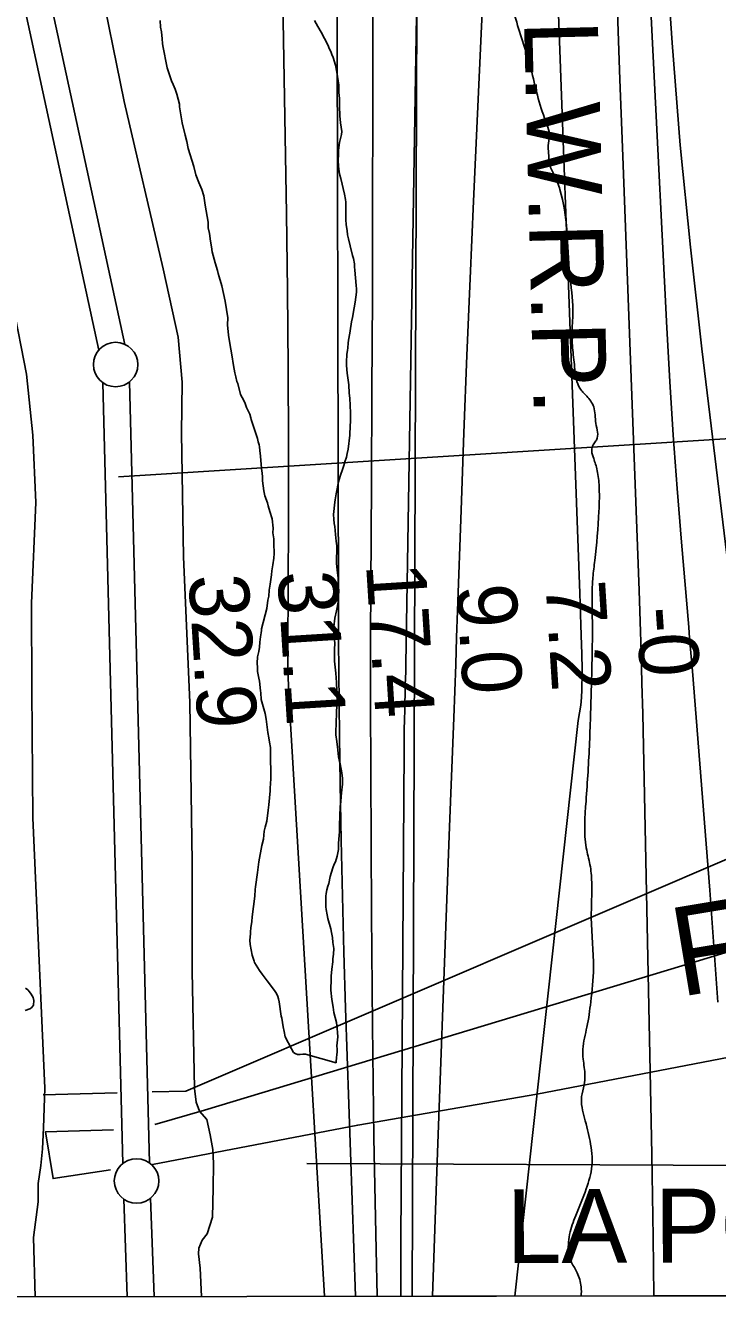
# Model space of a CAD drawing. Extents: x 3313442 to 3351311, y 721974 to 747360.
# Drawn here: x 3321997 to 3322775, y 727351 to 728787 of the extents above; entities that cross this region are included whole.
import ezdxf

# ---------------------------------------------------------------- set-up
doc = ezdxf.new("R2010")
doc.units = 0
for name, color, linetype in [('V-CHAN-NAID', 7, 'Continuous'), ('V-GRID-FRAM', 7, 'Continuous'), ('V-LEVE-TOET', 7, 'Continuous'), ('V-RIVR-EDGE', 7, 'Continuous'), ('V-RIVR-RANG', 7, 'Continuous'), ('V-RRAP-FSHR', 7, 'Continuous'), ('V-SITE-VEGE', 7, 'Continuous'), ('V-SURV-LINE', 7, 'Continuous'), ('V-TOPO-DPTH', 7, 'Continuous'), ('V-TOPO-MAJR', 7, 'Continuous'), ('V-TOPO-MINR', 7, 'Continuous'), ('V-TOPO-WATR', 7, 'Continuous'), ('V-TOPO-WATR-IDEN', 7, 'Continuous'), ('V-UTIL-IDEN', 7, 'Continuous'), ('V-UTIL-LINE', 7, 'Continuous')]:
    doc.layers.add(name, color=color, linetype=linetype)

msp = doc.modelspace()

# ---------------------------------------------------------------- linework, layer by layer
at = {"layer": 'V-GRID-FRAM'}
msp.add_lwpolyline([(3317558.4, 745536.3), (3349037, 745582.1), (3349071.4, 727396.8), (3317576.9, 727351), (3317558.4, 745536.3)], dxfattribs=at)
at = {"layer": 'V-LEVE-TOET'}
for points in [[(3322194.5, 727357.7), (3322192.8, 727389.4), (3322191.2, 727405.8), (3322191.6, 727411.9), (3322195, 727421.1), (3322200.8, 727428.3), (3322206.6, 727446.9), (3322207.4, 727479.7), (3322208, 727507.4), (3322207.1, 727523.1), (3322204.3, 727539.4), (3322200.4, 727556.6), (3322192.3, 727566.3), (3322188.6, 727576.1), (3322186.6, 727591.5), (3322184.1, 727723.8), (3322183.8, 727846.4), (3322181.2, 728025.8), (3322174, 728189.6), (3322172, 728328.7), (3322172.5, 728385.9), (3322168.1, 728436.7), (3322151.4, 728513.4), (3322107.3, 728701.9), (3322077.7, 728847.6)], [(3321914.5, 728813), (3321936.1, 728698.3), (3321966.6, 728552.6), (3321997.7, 728394.9), (3322004.8, 728326.6), (3322008.2, 728250.6), (3322003.2, 728137.7), (3322003.5, 728039.9), (3322004.9, 727896), (3322013.6, 727693.4), (3322018.2, 727592), (3322016.8, 727547.4), (3322015.7, 727523.9), (3322013.9, 727505.1), (3322010.8, 727484.9), (3322010.6, 727464.3), (3322005.5, 727424.2), (3322007.5, 727357.5)]]:
    msp.add_lwpolyline(points, dxfattribs=at)
at = {"layer": 'V-RIVR-EDGE'}
msp.add_spline([(3322512.8, 729081.8), (3322515.6, 729043.4), (3322518.8, 728981.6), (3322524.4, 728921.9), (3322530.2, 728886.2), (3322534.6, 728860.1), (3322542, 728820.3), (3322546.9, 728797.9), (3322563.8, 728741.9), (3322580.2, 728683), (3322585.6, 728662.7), (3322584.3, 728652.3), (3322584.7, 728644), (3322585.9, 728630.8), (3322591.3, 728618.7), (3322597.4, 728602.6), (3322605.2, 728557), (3322608.4, 728506.8), (3322612, 728467.4), (3322611.1, 728443.4), (3322611.9, 728422.2), (3322614.3, 728400.3), (3322619.7, 728379.5), (3322627.5, 728370.4), (3322635.4, 728358.3), (3322637.8, 728339.7), (3322638.6, 728321), (3322635.7, 728316.9), (3322633.2, 728311.1), (3322634.8, 728302), (3322638.9, 728288.7), (3322641.4, 728270.9), (3322641.3, 728240.6), (3322636.6, 728185.5), (3322634.5, 728166.4), (3322633.9, 728116.3), (3322632.9, 728048.3), (3322630.7, 727980.8), (3322629, 727948), (3322626.8, 727914.9), (3322627.1, 727862.2), (3322631.2, 727843.6), (3322633.2, 727823.7), (3322632.7, 727783.5), (3322635.1, 727727.1), (3322632.1, 727689), (3322627.8, 727660.8), (3322623.2, 727635.9), (3322623.6, 727624.7), (3322625.6, 727606.1), (3322624.8, 727595.7), (3322621.8, 727582.5), (3322625.1, 727558.4), (3322631.3, 727532.3), (3322633.3, 727504.5), (3322627, 727478.8), (3322615.3, 727449), (3322608.2, 727427.5), (3322606.9, 727415.9), (3322606.9, 727408.4), (3322610.6, 727396), (3322616.8, 727384.4), (3322621.3, 727368.6), (3322621.4, 727358.3)], degree=3, dxfattribs=at)
at = {"layer": 'V-RIVR-RANG'}
msp.add_line((3322101.2, 728279.7), (3322899.6, 728329.5), dxfattribs=at)
at = {"layer": 'V-RRAP-FSHR'}
msp.add_lwpolyline([(3322437.9, 729220.8), (3322431.3, 727358.1)], dxfattribs=at)
at = {"layer": 'V-SITE-VEGE'}
for points in [[(3322228.4, 728416.9), (3322226.1, 728429.7), (3322224.9, 728438.8), (3322223.8, 728450.4), (3322223.9, 728458.6), (3322221.1, 728477.2), (3322217.2, 728494.6), (3322214.4, 728504.5), (3322213.2, 728508.2), (3322212.4, 728511.6), (3322209.6, 728520.2), (3322206.4, 728532.7), (3322205.6, 728538.4), (3322204.5, 728544.6), (3322203.3, 728553.3), (3322202.1, 728559.5), (3322201.8, 728566.1), (3322198.6, 728585.1), (3322197.1, 728595.5), (3322194.7, 728602.9), (3322191.5, 728610.8), (3322188.2, 728619.1), (3322185.8, 728628.6), (3322179.4, 728648.9), (3322177.9, 728656.7), (3322175.9, 728663.8), (3322172.7, 728677.8), (3322169.6, 728695.6), (3322169.6, 728698.9), (3322166.8, 728710.1), (3322164.8, 728715.5), (3322162.4, 728720.8), (3322160.8, 728725), (3322157.9, 728732.9), (3322155.9, 728739.5), (3322150.8, 728764.3), (3322150.4, 728766.8), (3322150.1, 728772.1), (3322149.3, 728780), (3322148.5, 728785.3), (3322147.8, 728792.8)], [(3322321.5, 728792.8), (3322325.1, 728786.1), (3322329.1, 728779.6), (3322336.5, 728765.5), (3322338.3, 728760.6), (3322339.7, 728757.8), (3322341.1, 728754.5), (3322342.3, 728751.3), (3322344.9, 728742.6), (3322346.7, 728734.7), (3322348.7, 728720.3), (3322349, 728711.9), (3322349.4, 728705.2), (3322349.4, 728696.4), (3322350, 728685.5), (3322350.8, 728677.7), (3322352.3, 728668), (3322351.8, 728664.8), (3322350.6, 728660.3), (3322349.7, 728655.7), (3322348.9, 728649.9), (3322348.3, 728646.5), (3322348.3, 728642.6), (3322348.1, 728635.4), (3322348.4, 728629.1), (3322349.2, 728622.6), (3322349.9, 728618.8), (3322350.9, 728615.1), (3322355.2, 728597.6), (3322356.3, 728591.7), (3322356.6, 728588.4), (3322356.7, 728583), (3322356.6, 728568.9), (3322356.9, 728563.1), (3322358.1, 728556.6), (3322358.6, 728551.8), (3322359.6, 728547.1), (3322361.7, 728539.5), (3322364.3, 728528.6), (3322365.3, 728525.1), (3322366.4, 728519.2), (3322366.3, 728515.8), (3322367, 728512), (3322368.5, 728494.8), (3322368.6, 728491), (3322368.6, 728487.4), (3322367.2, 728476.1), (3322365.9, 728469.6), (3322364.2, 728458.7), (3322363.2, 728454), (3322361.5, 728443.8), (3322361.3, 728441.3), (3322359.6, 728433.2), (3322359.4, 728429.8), (3322358.8, 728424.8), (3322358.6, 728421.6), (3322357.9, 728417.5), (3322357.4, 728408.7), (3322357.6, 728404.7), (3322358.2, 728396.1), (3322360, 728383), (3322360.5, 728373.6), (3322361.2, 728368.2), (3322361.9, 728351.5), (3322361.8, 728341.5), (3322361.4, 728337.3), (3322361.1, 728326.4), (3322359.5, 728310.8), (3322358.2, 728305.9), (3322357.3, 728301.8), (3322355.6, 728296.3), (3322354.3, 728292.5), (3322353.4, 728288.9), (3322350.5, 728280.3), (3322348.6, 728274.1), (3322345.8, 728260.6), (3322344.8, 728253.6), (3322343.9, 728248.1), (3322343.5, 728244.1), (3322343, 728237.1), (3322343.2, 728232.1), (3322343.7, 728227.2), (3322344.2, 728223.8), (3322345.2, 728214.8), (3322345.8, 728207.3)], [(3322281, 727692.6), (3322280.2, 727695), (3322278.6, 727698.4), (3322276.5, 727701.7), (3322268.4, 727712.9), (3322262.7, 727720.4), (3322259.8, 727724.5), (3322254.1, 727733.3), (3322253.8, 727734.9), (3322251.3, 727741.5), (3322249, 727753.5), (3322248.6, 727758.5), (3322249.5, 727765.5), (3322249.5, 727768), (3322250, 727772.5), (3322250.9, 727779.5), (3322251.3, 727784.9), (3322252.7, 727796.4), (3322254.4, 727808), (3322254.9, 727815.4), (3322255, 727818.3), (3322257.2, 727834.7), (3322258.9, 727846.7), (3322262.4, 727864.8), (3322264.1, 727872.2), (3322265, 727880.9), (3322265.9, 727885.4), (3322268, 727892.4), (3322269.4, 727904.8), (3322270.3, 727910.6), (3322271.7, 727926.6), (3322271.7, 727929.5), (3322272.2, 727939.8), (3322272.3, 727946), (3322272, 727964.2), (3322272.1, 727975.3), (3322270.9, 727981.1), (3322270.2, 727986.1), (3322269, 727991.9), (3322267, 728007.2), (3322265.9, 728013.4), (3322261.5, 728029.1), (3322261.1, 728036.5), (3322260.7, 728039), (3322259.6, 728049.7), (3322258.8, 728053), (3322257.2, 728060.5), (3322257.3, 728065), (3322256.9, 728070), (3322257.4, 728077), (3322258.7, 728083.2), (3322259.6, 728088.1), (3322260, 728093.5), (3322260.9, 728099.7), (3322261.4, 728104.2), (3322261.8, 728106.7), (3322261.8, 728108.7), (3322267.8, 728131.4), (3322269.1, 728140.8), (3322270, 728145.4), (3322270.5, 728152), (3322271.8, 728159), (3322273.1, 728169.3), (3322273.6, 728173.8), (3322274.5, 728180.8), (3322275.8, 728188.2), (3322276.2, 728193.2), (3322275.9, 728204.7), (3322275.6, 728209.7), (3322274.8, 728216.7), (3322274.9, 728221.7), (3322273.7, 728232.4), (3322271.3, 728240.7), (3322269.3, 728246.9), (3322268.5, 728250.2), (3322265.7, 728258.1), (3322264.5, 728263.9), (3322263, 728275), (3322263, 728279.6), (3322262.6, 728283.7), (3322261.9, 728289.1), (3322260.8, 728302.7), (3322260, 728309.3), (3322259.6, 728313.4), (3322259.2, 728315.5), (3322258, 728318.8), (3322257.2, 728322.9), (3322256, 728327.1), (3322250.4, 728344.1), (3322250, 728346.1), (3322248.8, 728349.9), (3322245.2, 728357.7), (3322243.2, 728363.1), (3322240.3, 728368.9), (3322238.3, 728372.2), (3322235.1, 728384.6), (3322234.3, 728386.7), (3322233.1, 728392.1), (3322231.9, 728396.6), (3322230.4, 728404.9), (3322228.4, 728416.9)], [(3322345.8, 728207.3), (3322346.5, 728202.1), (3322346.3, 728182.1), (3322347.1, 728174.9), (3322347.9, 728165.8), (3322348.1, 728160.4), (3322348.7, 728151), (3322348.5, 728145.7), (3322347.9, 728138.5), (3322346.3, 728128.8), (3322344.5, 728120.7), (3322343.1, 728111), (3322343.1, 728105.3), (3322343.4, 728099.2), (3322344.2, 728092.7), (3322343.8, 728085.5), (3322343.9, 728080.3), (3322343.8, 728072.2), (3322345.5, 728058.8), (3322346.1, 728048.3), (3322346.4, 728039), (3322346.9, 728035.8), (3322346.8, 728025), (3322346.2, 728016.4), (3322346.1, 728011.2), (3322345.7, 728006), (3322345.6, 727989.4), (3322346.6, 727982.1), (3322347.6, 727972.4), (3322348.6, 727964.8), (3322349.6, 727959.6), (3322350.5, 727956.7), (3322352.2, 727946.6), (3322352.8, 727940.2), (3322352.9, 727934.1), (3322352.7, 727930.5), (3322352.2, 727927.4), (3322351.4, 727920.1), (3322351.1, 727914), (3322350.5, 727908.8), (3322349.6, 727887.8), (3322349.7, 727880.8), (3322349.2, 727876.1), (3322348.4, 727867.5), (3322348.3, 727860.3), (3322346.8, 727852.9), (3322344.9, 727846.7), (3322343.6, 727844), (3322342.2, 727839.9), (3322339.2, 727830.2), (3322337.5, 727822.3), (3322336.4, 727819.1), (3322335.5, 727815), (3322334.7, 727811), (3322334.3, 727807.8), (3322334.3, 727801.3), (3322334.4, 727796.1), (3322334.7, 727793.1), (3322335.6, 727787.1), (3322336.6, 727782.8), (3322339.7, 727771.3), (3322340.6, 727767.2), (3322341.6, 727761.6), (3322342.1, 727755.7), (3322343.1, 727749), (3322343, 727742.7), (3322342.1, 727737.5), (3322341.9, 727734.1), (3322340.9, 727726), (3322340.7, 727721.9), (3322340.3, 727718.5), (3322340.1, 727715.4), (3322340, 727702.3), (3322340.8, 727691.9), (3322342.3, 727683.1), (3322343.1, 727677.2), (3322346.3, 727665.8), (3322347.1, 727659), (3322347.4, 727654.5), (3322347.6, 727649.8), (3322346.7, 727639.6), (3322346.9, 727635.8), (3322346.9, 727632.8), (3322346.6, 727629.7), (3322346.1, 727626.7), (3322345.9, 727621.8), (3322345.7, 727620.7), (3322311.4, 727630.4), (3322308.5, 727630.4), (3322305.2, 727630), (3322302.3, 727630), (3322299.8, 727630.9), (3322297.8, 727632.2), (3322295.7, 727636.3), (3322288.4, 727649.6), (3322287.3, 727655.8), (3322286.1, 727661.1), (3322284.9, 727670.7), (3322284.1, 727673.1), (3322281.8, 727689.3), (3322281, 727692.6)], [(3321996.5, 727704.5), (3321999, 727702.7), (3322001.2, 727700.2), (3322003, 727697.6), (3322005, 727694.1), (3322006, 727690.8), (3322005.7, 727685.5), (3322003.1, 727682.4), (3322001.3, 727681.2), (3321996.2, 727679.5)]]:
    msp.add_lwpolyline(points, dxfattribs=at)
at = {"layer": 'V-SURV-LINE'}
for points in [[(3322079, 728422.2), (3321968.5, 728932.8)], [(3321997.8, 728939.2), (3322108.3, 728428.6)], [(3322113.3, 728386.3), (3322135.8, 727508.1)], [(3322105.8, 727507.3), (3322083.4, 728385.5)], [(3322111, 727357.6), (3322107.1, 727467.2)], [(3322137.1, 727468.3), (3322141.1, 727357.6)]]:
    msp.add_lwpolyline(points, dxfattribs=at)
for centre in [(3322097.8, 728405.9), (3322121.4, 727487.7)]:
    msp.add_circle(centre, 25, dxfattribs=at)
at = {"layer": 'V-TOPO-DPTH'}
for points in [[(3322521, 729040.3), (3322500.3, 728589.5), (3322496.5, 728502.7), (3322492.9, 728415.9), (3322489.5, 728329.1), (3322486.3, 728242.3), (3322482.4, 728128.8), (3322481.3, 728098.8), (3322480.2, 728068.7), (3322479.1, 728038.7), (3322478, 728008.7), (3322473.2, 727885.8), (3322469.8, 727794.3), (3322466.4, 727702.8), (3322463.1, 727611.3), (3322459.8, 727519.8), (3322454.2, 727358.1), (3322702.9, 727358.5)], [(3322715.8, 728882.5), (3322723.6, 728767.6), (3322732.8, 728652.7), (3322744.2, 728538.1), (3322756.9, 728423.5), (3322788, 728166.6)], [(3322715.8, 728882.5), (3322723.6, 728767.6), (3322732.8, 728652.7), (3322744.2, 728538.1), (3322756.9, 728423.5), (3322788, 728166.6)], [(3322702.9, 727358.5), (3322702.1, 727424.3), (3322700.6, 727517.6), (3322698.8, 727610.9), (3322690.5, 728013), (3322689.7, 728047.6), (3322688.7, 728082.3), (3322687.6, 728116.9), (3322686.4, 728151.6), (3322667.7, 728650.1), (3322664.9, 728726.4), (3322662.1, 728802.7)], [(3322702.9, 727358.5), (3322702.1, 727424.3), (3322700.6, 727517.6), (3322698.8, 727610.9), (3322690.5, 728013), (3322689.7, 728047.6), (3322688.7, 728082.3), (3322687.6, 728116.9), (3322686.4, 728151.6), (3322667.7, 728650.1), (3322664.9, 728726.4), (3322662.1, 728802.7)], [(3322861.6, 727358.7), (3322702.9, 727358.5)]]:
    msp.add_lwpolyline(points, dxfattribs=at)
at = {"layer": 'V-TOPO-MAJR'}
msp.add_lwpolyline([(3322346.5, 728937), (3322348.4, 728132), (3322348.6, 728096.1), (3322348.8, 728060.2), (3322349.2, 728024.3), (3322349.6, 727988.3), (3322350.4, 727934.1), (3322351.5, 727871.1), (3322352.8, 727808.1), (3322354.5, 727745.1), (3322356.5, 727682.1), (3322367.4, 727358)], dxfattribs=at)
at = {"layer": 'V-TOPO-MINR'}
for points in [[(3322440.2, 729049.6), (3322424.2, 728069), (3322424.2, 728065.1), (3322424.1, 728061.2), (3322423.8, 728052.5), (3322423.6, 728046.2), (3322423.5, 728039.9), (3322423.3, 728033.6), (3322423.1, 728027.3), (3322422.9, 728017.6), (3322422.6, 728006.4), (3322422.4, 727995.3), (3322422.3, 727984.1), (3322422.2, 727973), (3322418.5, 727421.5), (3322418.4, 727358)], [(3322586.3, 729055), (3322619.8, 728148.7), (3322620.2, 728136.9), (3322620.6, 728125.1), (3322621, 728113.3), (3322621.4, 728101.5), (3322622.1, 728080.2), (3322622.1, 728076.8), (3322622.2, 728075.7), (3322622.3, 728067.7), (3322622.3, 728062.6), (3322622.3, 728057.5), (3322622.3, 728052.4), (3322622.1, 728047.3), (3322621.9, 728040.1), (3322621.5, 728031.4), (3322620.8, 728022.7), (3322619.6, 728014.1), (3322618.1, 728005.5), (3322546.8, 727358.2)], [(3322686.9, 729058), (3322717.7, 728447.2), (3322721, 728386.9), (3322724.8, 728326.6), (3322729.2, 728266.4), (3322734.1, 728206.2), (3322742.3, 728110.6), (3322743.3, 728098.3), (3322744.4, 728085.9), (3322745.4, 728073.5), (3322746.4, 728061.2), (3322765.8, 727814.9), (3322775.1, 727688.8)], [(3322387.1, 729035.2), (3322386.9, 728691.5), (3322386.8, 728586.7), (3322386.5, 728481.8), (3322386.1, 728377), (3322385.6, 728272.2), (3322384.6, 728098.4), (3322384.5, 728080.5), (3322384.5, 728062.5), (3322384.5, 728044.5), (3322384.6, 728026.6), (3322385.6, 727788), (3322386.6, 727662.1), (3322388.3, 727536.2), (3322390.8, 727410.4), (3322392.1, 727358)], [(3322521, 729040.3), (3322500.3, 728589.5), (3322496.5, 728502.7), (3322492.9, 728415.9), (3322489.5, 728329.1), (3322486.3, 728242.3), (3322482.4, 728128.8), (3322481.3, 728098.8), (3322480.2, 728068.7), (3322479.1, 728038.7), (3322478, 728008.7), (3322473.2, 727885.8), (3322469.8, 727794.3), (3322466.4, 727702.8), (3322463.1, 727611.3), (3322459.8, 727519.8), (3322454.2, 727358.1)], [(3322282.1, 729031.6), (3322289.9, 728575.8), (3322291.1, 728489.2), (3322291.9, 728402.7), (3322292.2, 728316.1), (3322292.1, 728229.6), (3322291.5, 728085.6), (3322291.6, 728071), (3322291.9, 728056.5), (3322292.4, 728041.9), (3322293.1, 728027.4), (3322332.8, 727357.9)], [(3322715.8, 728882.5), (3322723.6, 728767.6), (3322732.8, 728652.7), (3322744.2, 728538.1), (3322756.9, 728423.5), (3322788, 728166.6)]]:
    msp.add_lwpolyline(points, dxfattribs=at)
at = {"layer": 'V-TOPO-WATR'}
msp.add_lwpolyline([(3322662.1, 728802.7), (3322664.9, 728726.4), (3322667.7, 728650.1), (3322686.4, 728151.6), (3322687.6, 728116.9), (3322688.7, 728082.3), (3322689.7, 728047.6), (3322690.5, 728013), (3322698.8, 727610.9), (3322700.6, 727517.6), (3322702.1, 727424.3), (3322702.9, 727358.5)], dxfattribs=at)
at = {"layer": 'V-UTIL-LINE'}
msp.add_line((3322313, 727507.2), (3325205.1, 727494.1), dxfattribs=at)
for points in [[(3324190.5, 728452.5), (3322176.8, 727588.8), (3322138.9, 727587.8)], [(3325299.9, 727544.4), (3324792.6, 727707.7), (3324744.8, 727738.3), (3324706.9, 727795.7), (3324606.7, 727957.2), (3324540.9, 728072.8), (3324503.7, 728158.6), (3324460, 728199.3), (3324435.7, 728211.7), (3324384.7, 728222.3), (3324332.1, 728212.8), (3322197.8, 727567.2), (3322142.1, 727551.3)], [(3322139.5, 727506.2), (3322370.1, 727550.6), (3322571.3, 727585.2), (3324361.9, 727929.9)], [(3322099.6, 727586.8), (3322016.3, 727584.6)], [(3322095.6, 727545.1), (3322019, 727542.8), (3322027.6, 727490.3), (3322092, 727500)]]:
    msp.add_lwpolyline(points, dxfattribs=at)

# ---------------------------------------------------------------- texts
at = {"layer": 'V-CHAN-NAID'}
msp.add_text('FORMOSA - PLANT (233.5)', height=100, rotation=9.4623, dxfattribs=at).set_placement((3322732.4, 727694.6))
at = {"layer": 'V-RIVR-RANG'}
for s, rotation, p in [('31.1', 273.5783, (3322279.8, 728172.4)), ('17.4', 273.5783, (3322379.4, 728181.2)), ('32.9', 273.5783, (3322179.8, 728168.5)), ('9.0', 273.5783, (3322481.1, 728157.4)), ('7.2', 273.5783, (3322581.1, 728161)), ('-0', 273.86, (3322682.9, 728132))]:
    msp.add_text(s, height=67, rotation=rotation, dxfattribs=at).set_placement(p)
at = {"layer": 'V-TOPO-WATR-IDEN'}
msp.add_text('L.W.R.P.', height=83, rotation=271.4406, dxfattribs=at).set_placement((3322557, 728792.5))
at = {"layer": 'V-UTIL-IDEN'}
msp.add_text('LA POWER & LIGHT. CO.', height=83, rotation=0.1831, dxfattribs=at).set_placement((3322537.5, 727395.3))

doc.saveas('drawing.dxf')
